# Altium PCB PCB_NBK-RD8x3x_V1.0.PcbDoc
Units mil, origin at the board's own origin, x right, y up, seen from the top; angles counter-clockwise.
Board outline 2760.94 x 3491.25 mil, 2 copper layers (Top Layer, Bottom Layer), stack 21 mil thick; 40 components, 63 nets, 291 pads, 93 vias.
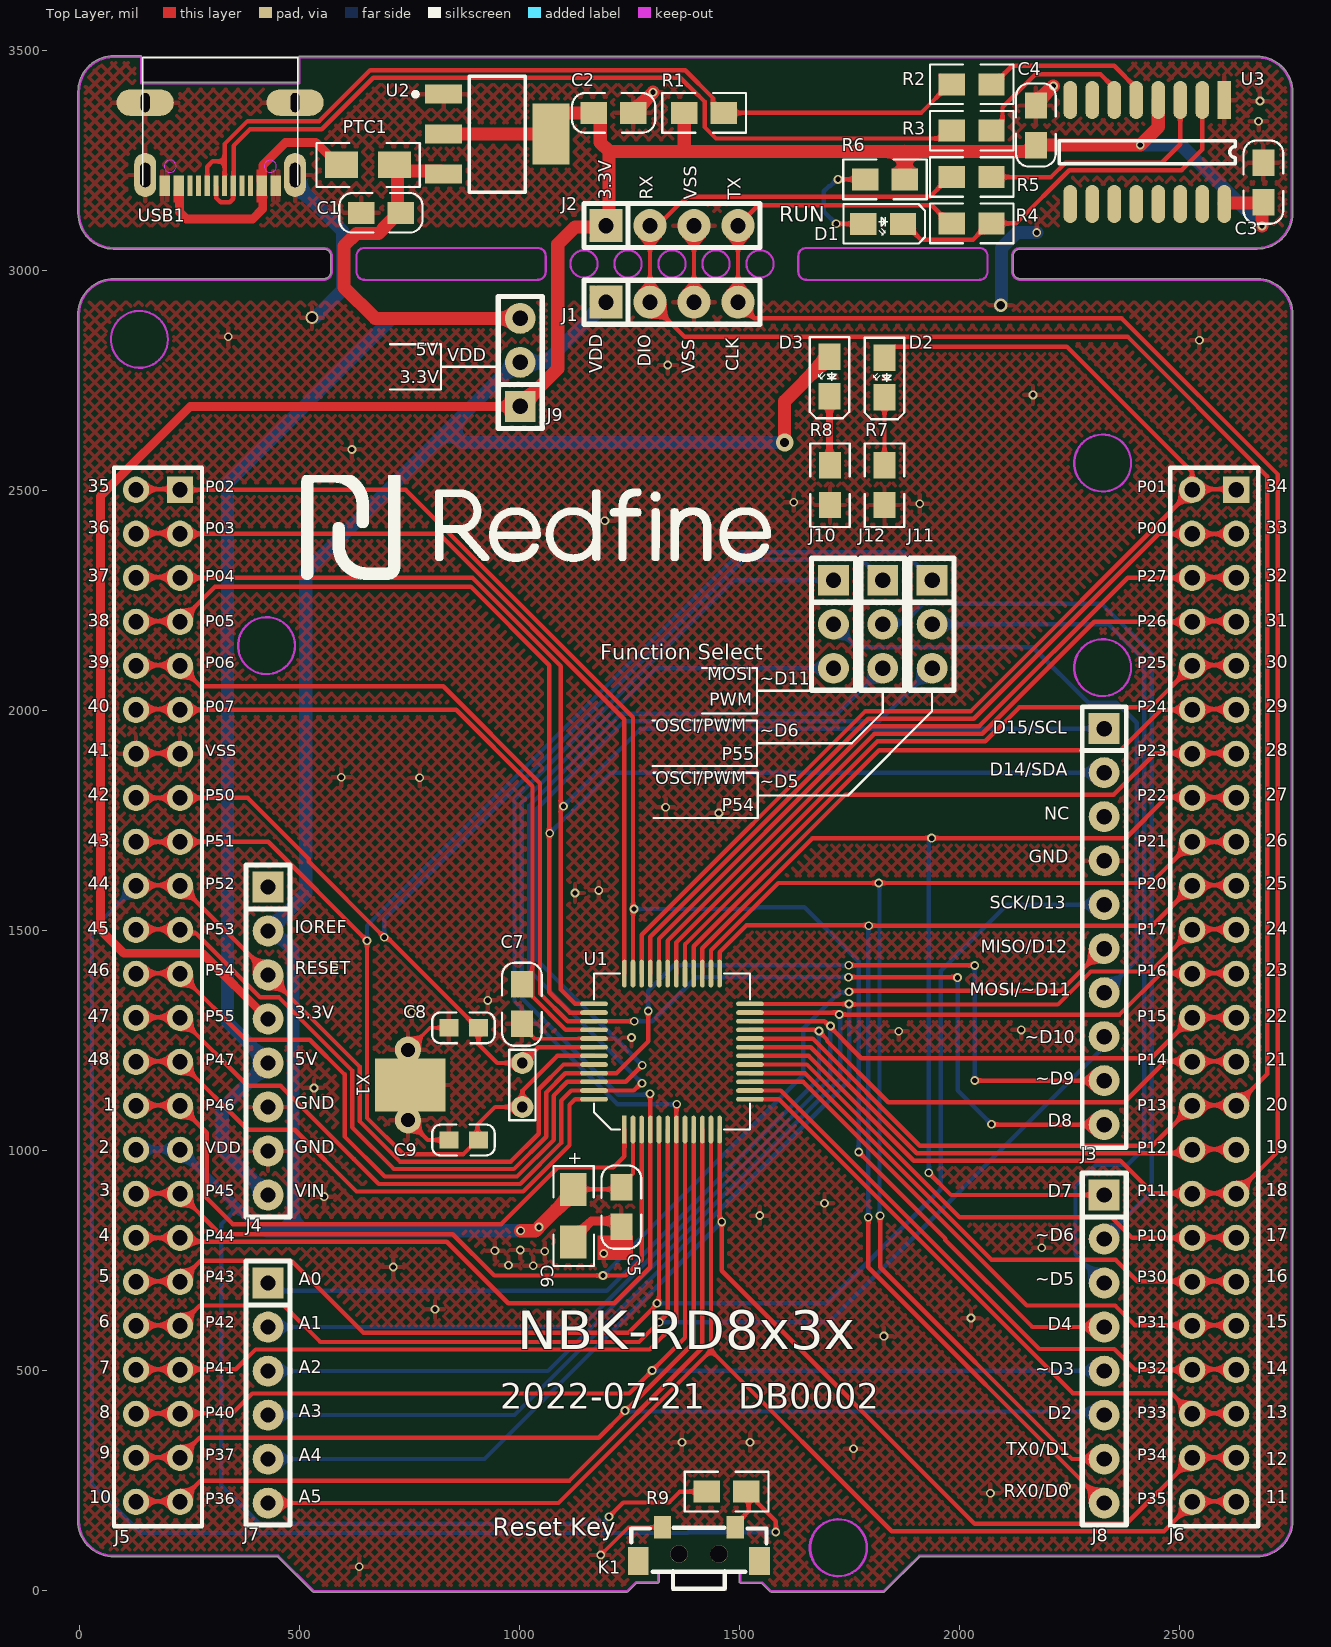
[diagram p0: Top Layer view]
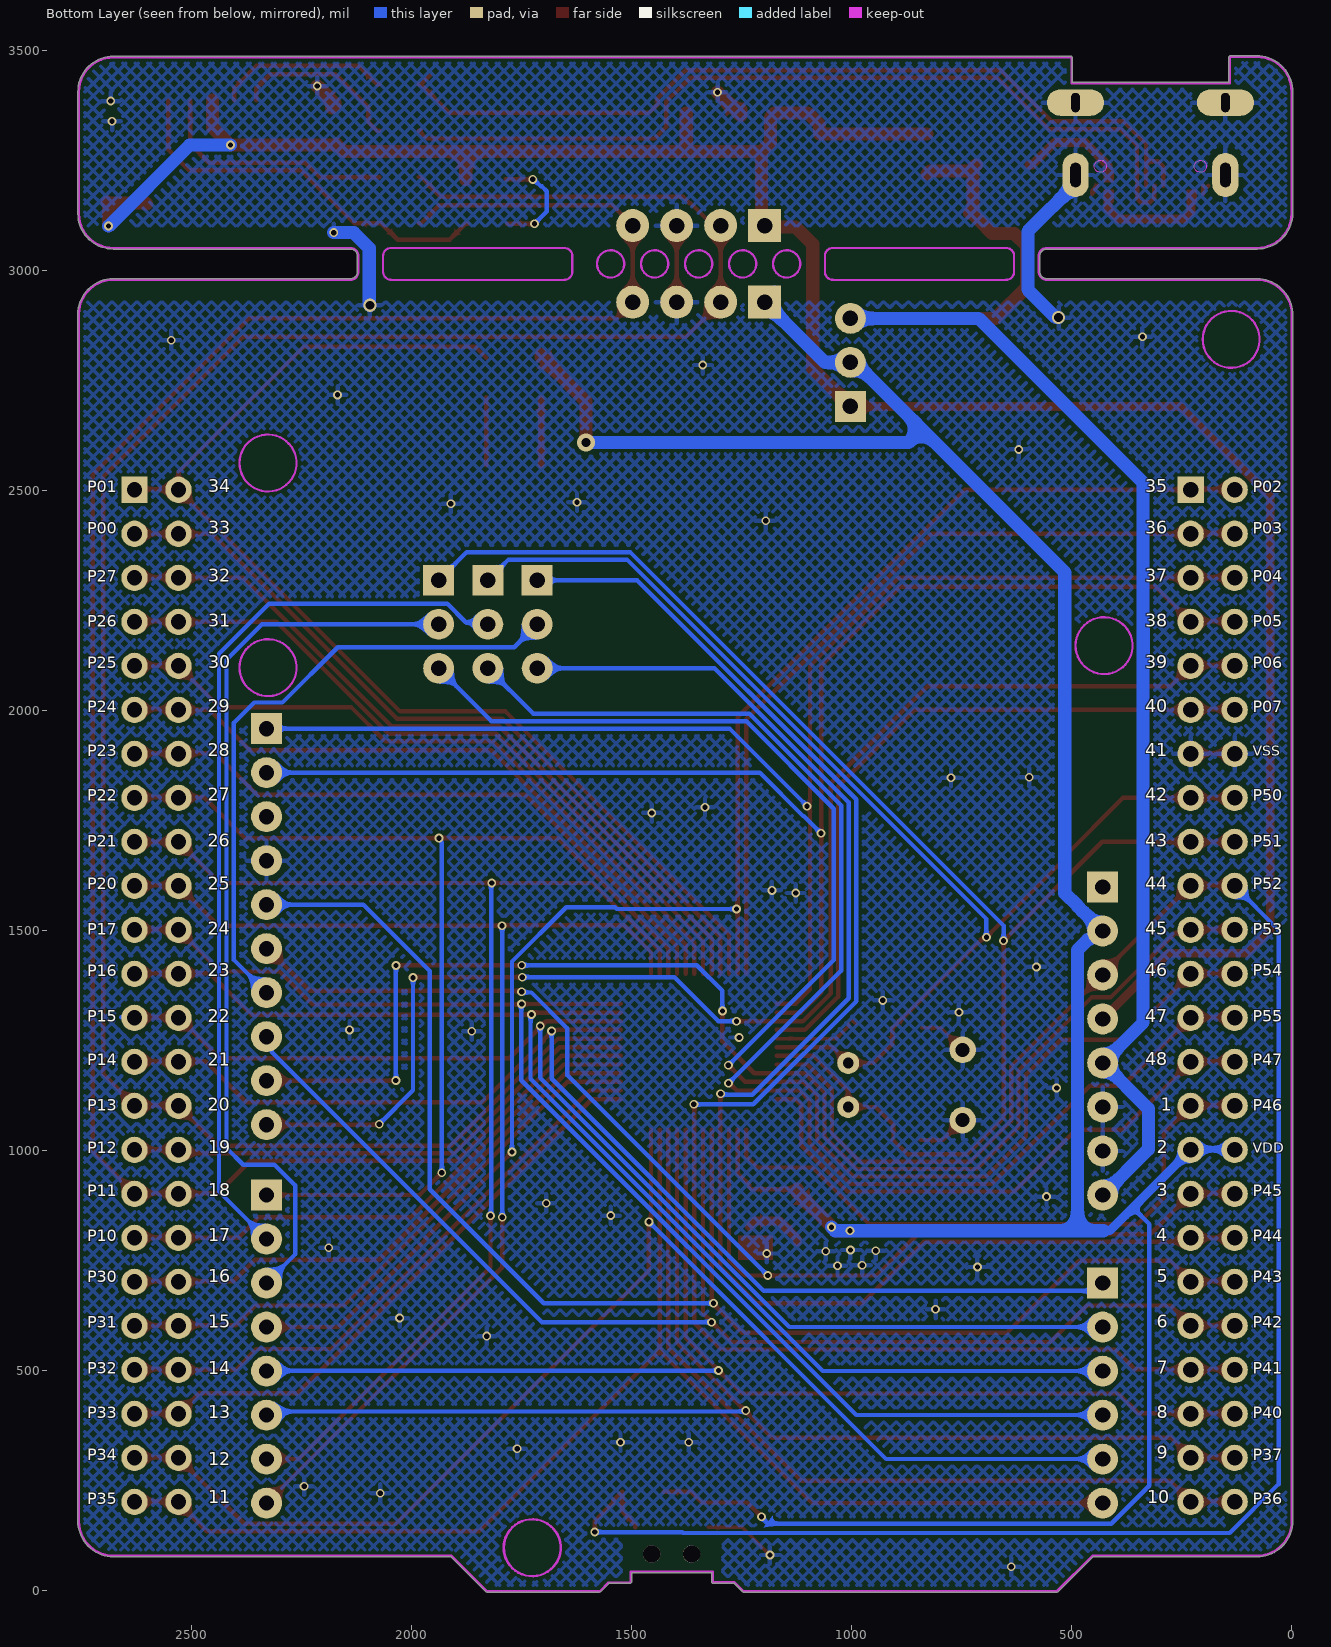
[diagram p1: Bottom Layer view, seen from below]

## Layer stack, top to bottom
Top Solder: solder mask 0.4, Solder Resist, Dk 3.5
Top Layer: signal copper 1.4
Dielectric 1: prepreg 2.8, PP-006, Dk 4.1
Dielectric1: dielectric 12.6, FR-4, Dk 4.8
Dielectric 2: prepreg 2.8, PP-006, Dk 4.1
Bottom Layer: signal copper 1.4
Bottom Solder: solder mask 0.4, Solder Resist, Dk 3.5

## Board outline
78.06,76.8 451.03,76.8 530.62,-2.79 532.39,-3.52 1245.4,-3.52 1247.18,-2.78 1266.44,16.48 1315,16.48 1317.51,19 1317.51,40.49 1499.49,40.49 1499.49,18.73 1502.36,16.21 1550.92,16.21 1570.18,-3.05 1573.1,-3.52 1828.45,-3.52 1830.23,-2.78 1909.81,76.8 2676.48,76.8 ccw(c2676.48,158.06) 2757.74,158.05 2757.74,2900.58 ccw(c2677.03,2900.58) 2677.58,2981.28 2676.95,2981.37 2138.15,2981.37 cw(c2138.15,2997) 2122.51,2997 2122.51,3033 cw(c2138.15,3033) 2138.15,3048.63 2676.95,3048.63 ccw(c2676.95,3129.34) 2757.66,3129.34 2757.66,3405.93 ccw(c2676.95,3405.93) 2676.95,3486.64 500,3486.64 497.49,3484.12 497.49,3427.52 142.51,3427.52 142.51,3485 139.78,3487.74 78.35,3487.74 ccw(c78.35,3406.48) -2.91,3406.48 -2.91,3129.89 ccw(c78.35,3129.89) 78.22,3048.63 555.95,3048.63 cw(c555.95,3033) 571.59,3033 571.59,2997 cw(c555.95,2997) 555.95,2981.37 555.06,2981.2 78.06,2981.2 ccw(c78.05,2899.94) -3.03,2905.23 -3.2,2904.31 -3.2,159 -3.2,158.05 ccw(c78.06,158.05)

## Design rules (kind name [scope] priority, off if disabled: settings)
Clearance Clearance_2 [(InComponent('U1') AND IsPad)] p1: gap=6 ignorepadtopadclearanceinfootprint=FALSE except(0: Arc-Hole Track-Hole SMDPad-Hole THPad-Hole Via-Hole Fill-Hole Poly-Hole Region-Hole Text-Hole)
Clearance Clearance_1 [All] p2: gap=7 ignorepadtopadclearanceinfootprint=FALSE except(0: Arc-Hole Track-Hole SMDPad-Hole THPad-Hole Via-Hole Fill-Hole Poly-Hole Region-Hole Text-Hole)
ComponentClearance [All] p1 off: gap=10 collisioncheckmode=3 verticalgap=10 showdistances=FALSE
Height [All] p1 off: minheight=0 maxheight=1000 prefheight=500
HoleSize [All] p1: absolutevalues=TRUE maxlimit=150 minlimit=1 maxpercent=80.000 minpercent=20.000
MinimumSolderMaskSliver [All] p1: minsoldermaskwidth=0
PolygonConnect [All] p1: connectstyle=Relief reliefconductorwidth=10 reliefentries=4 polygonreliefangle="90 Angle" airgapwidth=10
RoutingVias [All] p1: holewidth=28 width=50 viastyle="Through Hole" minholewidth=10 minwidth=20 maxholewidth=130 maxwidth=180
SilkToSilkClearance [All] p1 off: silktosilkclearance=0
SilkToSolderMaskClearance [IsPad] p1 off: minsilkscreentomaskgap=0 clearancetoexposedcopper=TRUE
SolderMaskExpansion [All] p1: expansion=4 istentingtop=FALSE
Width [All] p1: maxlimit=30 minlimit=5 preferedwidth=7
24 further rules are at their usual default settings.

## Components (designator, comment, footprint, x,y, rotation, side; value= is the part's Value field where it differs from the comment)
C1 "104" C0805 731,3131 r180 top
C2 "104" C0805 1169,3358 r0 top
C3 "104" C0805 2691,3155.2 r90 top
C4 "104" C0805 2174,3285 r90 top
C5 "104" C0805 1232,917 r270 top
C6 "10uF" A-3216 1123,912 r270 top
C7 "103" C0805 1006,1378 r270 top
C8 "10pF" C0603 907,1279 r180 top
C9 "10pF" C0603 907,1024 r180 top
D1 "LED-GREED" LED0805 1827,3106 r0 top
D2 "LED-GREED" LED0805 1830,2757 r270 top
D3 "LED-GREED" LED0805 1705,2759 r270 top
J1 "CON1*4" CON1*4(P=2.54) 1347,2928 r0 top
J2 "CON1*4" CON1*4(P=2.54) 1347,3102 r0 top
J3 "CON1*10" CON1*10(P=2.54) 2329,1509 r270 top
J4 "CON1*8" CON1*8(P=2.54) 429,1249 r270 top
J5 "CON2*24" CON2*24(P=2.54) 194,1351.5 r270 top
J6 "CON2*24" CON2*24(P=2.54) 2594,1351.5 r270 top
J7 "CON1*6" CON1*6(P=2.54) 429,449 r270 top
J8 "CON1*8" CON1*8(P=2.54) 2329,549 r270 top
J9 "CON1*3" CON1*3(P=2.54) 1002,2791 r90 top
J10 "CON1*3" CON1*3(P=2.54) 1714,2196 r270 top
J11 "CON1*3" CON1*3(P=2.54) 1938,2196 r270 top
J12 "CON1*3" CON1*3(P=2.54) 1826,2196 r270 top
K1 "单路开关" SW-SMD_UK-B0246-SP25Y 1408.28,105.64 r180 top
PTC1 "0.5A 6V 自恢复保险丝" R1206 596,3240 r0 top
R1 "1.5K" R0805 1375,3358 r0 top
R2 "22R" R0805 1983,3423 r0 top
R3 "22R" R0805 1983,3317.67 r0 top
R4 "100R" R0805 2073,3107 r180 top
R5 "100R" R0805 2073,3212.33 r180 top
R6 "2.2K" R0805 1876,3207 r180 top
R7 "5.1K" R0805 1830,2557 r270 top
R8 "5.1K" R0805 1706,2557 r270 top
R9 "1.5K" R0805 1516,225 r180 top
U1 "RD8T37P48" LQFP-48(7X7) 1347,1225 r90 top (schematic designator U?)
U2 "AMS1117-3.3V" SOT-223 950,3310 r270 top
U3 "CH340C" SOP16 2602,3387.22 r270 top
USB1 "TYPE-C" TYPE-C1 320.22,3287.01 r0 top
X1 "32.768K" 32768 1007,1199 r270 top

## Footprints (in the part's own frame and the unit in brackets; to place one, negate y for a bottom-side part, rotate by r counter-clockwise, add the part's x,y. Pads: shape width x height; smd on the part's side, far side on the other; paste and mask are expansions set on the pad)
32768 [mil] "32.768KHZ"
  round 60 hole 32: 0(-30,-260) 0(130,-260)
  rect 120x160 smd: 0(50,-255)
  round 50 hole 24: 1(0,0) 2(100,0)
  silkscreen extent -30,-30 130,30
A-3216 [mil]
  rect 75x60 smd: 1(0,0) 2(120,0)
  silkscreen extent -53,-45 174,47
C0603 [mm]
  rect 1.1x1 smd: 1(0,0) 2(1.7,0)
  silkscreen extent -0.94,-0.89 2.67,0.89
C0805 [mil]
  rect 60x50 smd: 1(0,0) 2(90,0)
  silkscreen extent -49,-45 140,45
CON1*3(P=2.54) [mil]
  rect 70x70 hole 35: 1(-100,0)
  round 70 hole 35: 2(0,0) 3(100,0)
  silkscreen extent -150,-50 150,50
CON1*4(P=2.54) [mil]
  rect 75x75 hole 35: 1(-150,0)
  round 75 hole 35: 2(-50,0) 3(50,0) 4(150,0)
  silkscreen extent -200,-50 200,50
CON1*6(P=2.54) [mil]
  rect 70x70 hole 35: 1(-250,0)
  round 70 hole 35: 2(-150,0) 3(-50,0) 4(50,0) 5(150,0) 6(250,0)
  silkscreen extent -300,-50 300,50
CON1*8(P=2.54) [mil]
  rect 70x70 hole 35: 1(-350,0)
  round 70 hole 35: 2(-250,0) 3(-150,0) 4(-50,0) 5(50,0) 6(150,0) 7(250,0) 8(350,0)
  silkscreen extent -400,-50 400,50
CON1*10(P=2.54) [mil]
  rect 70x70 hole 35: 1(-450,0)
  round 70 hole 35: 2(-350,0) 3(-250,0) 4(-150,0) 5(-50,0) 6(50,0) 7(150,0) 8(250,0) 9(350,0) 10(450,0)
  silkscreen extent -500,-50 502,50
CON2*24(P=2.54) [mil]
  rect 60x60 hole 35: 1(-1150,35)
  round 60 hole 35: 2(-1150,-65) 3(-1050,35) 4(-1050,-65) 5(-950,35) 6(-950,-65) 7(-850,35) 8(-850,-65) 9(-750,35) 10(-750,-65) 11(-650,35) 12(-650,-65) 13(-550,35) 14(-550,-65) 15(-450,35) 16(-450,-65) 17(-350,35) 18(-350,-65) 19(-250,35) 20(-250,-65) 21(-150,35) 22(-150,-65) 23(-50,35) 24(-50,-65) 25(50,35) 26(50,-65) 27(150,35) 28(150,-65) 29(250,35) 30(250,-65) 31(350,35) 32(350,-65) 33(450,35) 34(450,-65) 35(550,35) 36(550,-65) 37(650,35) 38(650,-65) 39(750,35) 40(750,-65) 41(850,35) 42(850,-65) 43(950,35) 44(950,-65) 45(1050,35) 46(1050,-65) 47(1150,35) 48(1150,-65)
  silkscreen extent -1200,-115 1205,85
LED0805 [mil]
  rect 60x50 smd: 1(-45,0) 2(45,0)
  silkscreen extent -90,-45 95,45
LQFP-48(7X7) [mm]
  rect 1.6x0.27 smd: 1(-4.5,2.75)
  oval 1.6x0.27 smd: 2(-4.5,2.25) 3(-4.5,1.75) 4(-4.5,1.25) 5(-4.5,0.75) 6(-4.5,0.25) 7(-4.5,-0.25) 8(-4.5,-0.75) 9(-4.5,-1.25) 10(-4.5,-1.75) 11(-4.5,-2.25) 12(-4.5,-2.75) 25(4.5,-2.75) 26(4.5,-2.25) 27(4.5,-1.75) 28(4.5,-1.25) 29(4.5,-0.75) 30(4.5,-0.25) 31(4.5,0.25) 32(4.5,0.75) 33(4.5,1.25) 34(4.5,1.75) 35(4.5,2.25) 36(4.5,2.75)
  oval 0.27x1.6 smd: 13(-2.75,-4.5) 14(-2.25,-4.5) 15(-1.75,-4.5) 16(-1.25,-4.5) 17(-0.75,-4.5) 18(-0.25,-4.5) 19(0.25,-4.5) 20(0.75,-4.5) 21(1.25,-4.5) 22(1.75,-4.5) 23(2.25,-4.5) 24(2.75,-4.5) 37(2.75,4.5) 38(2.25,4.5) 39(1.75,4.5) 40(1.25,4.5) 41(0.75,4.5) 42(0.25,4.5) 43(-0.25,4.5) 44(-0.75,4.5) 45(-1.25,4.5) 46(-1.75,4.5) 47(-2.25,4.5) 48(-2.75,4.5)
  silkscreen extent -4.5,-4.5 4.5,4.5
R0805 [mil]
  rect 60x50 smd: 1(0,0) 2(90,0)
  silkscreen extent -50,-45 140,45
R1206 [mil]
  rect 75x60 smd: 1(0,0) 2(120,0)
  silkscreen extent -57,-50 178,50
SOP16 [mm]
  rect 2.2x0.8 smd: 1(0,0)
  oval 2.2x0.8 smd: 2(0,-1.27) 3(0,-2.54) 4(0,-3.81) 5(0,-5.08) 6(0,-6.35) 7(0,-7.62) 8(0,-8.89) 9(6,-8.89) 10(6,-7.62) 11(6,-6.35) 12(6,-5.08) 13(6,-3.81) 14(6,-2.54) 15(6,-1.27) 16(6,0)
  silkscreen extent 2.33,-9.53 3.67,0.64
SOT-223 [mm]
  rect 1.1x2.15 smd: 1(-2.3,-3.1) 2(0,-3.1) 3(2.3,-3.1)
  rect 3.5x2.15 smd: 2(0,3.1)
  silkscreen extent -3.35,-4.85 3.35,1.63
SW-SMD_UK-B0246-SP25Y [mm]
  rect 1x1.3 smd: 1(2.1,-0.975) 2(-2.1,-0.975)
  rect 1.2x1.6 smd: 3(-3.5,0.975) 4(3.5,0.975)
  round 1 hole 1 unplated: ""(-1.15,0.575) ""(1.15,0.575)
  silkscreen extent -3.9,-0.95 3.9,2.57
TYPE-C1 [mm]
  oval 3.302x1.524 / inner oval 1.27x2.54 / far side oval 3.302x1.524 hole 0.5 slot 1.1 at 90 deg: 1(-4.325,2.4) 3(4.325,2.4)
  oval 1.27x2.54 / inner oval 1.27x2.54 / far side oval 1.524x2.54 hole 0.6 slot 1.4 at 90 deg: 2(-4.325,-1.78) 4(4.325,-1.78)
  rect 0.3x1.2 smd: A1(3.355,-2.4) A4(2.555,-2.4) A5(1.255,-2.4) A6(0.255,-2.4) A7(-0.245,-2.4) A8(-1.245,-2.4) A9(-2.545,-2.4) A12(-3.345,-2.4) B1(-3.045,-2.4) B4(-2.245,-2.4) B5(-1.745,-2.4) B6(-0.745,-2.4) B7(0.755,-2.4) B8(1.755,-2.4) B9(2.255,-2.4) B12(3.055,-2.4)
  Keep-Out Layer circle w0.05: c-2.885,-1.28 r0.35
  Keep-Out Layer circle w0.05: c2.895,-1.28 r0.35
  silkscreen extent -4.47,-2.35 4.48,5

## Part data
C1 C2 C3 C4 C5 C7 C8 C9: library part CAP1, "贴片电容"
C6: library part T-A/4.7uF/16V
D1 D2: library part LED-CP, "蓝色"
D3: library part LED-CP, "红色"
K1: library part KEY-6
PTC1: library part PTC-MZ11-06A200-400RM, "6V 500mA PTC自恢复保险丝"
R1 R2 R3 R4 R5 R6 R7 R8 R9: library part R0805
U1: "电压:2.0V-5.5V;ROM:128KB;RAM:内部256B+外部8KB+ PWM&LCD 80B;32/16/8/4MHz"
U2: library part LDO-SPX1117M3, "LDO；1A；SOT-223-3"
USB1: library part TYPE-C1, "Type-c母座16pin 快充闪充usb3.0沉板母座连接器"
X1: library part CRYSTAL

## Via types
v1: diameter 20, hole 12, Top Layer to Bottom Layer, 90 vias
v2: diameter 30, hole 20, Top Layer to Bottom Layer, 2 vias
v3: diameter 40, hole 20, Top Layer to Bottom Layer, tented both sides, 1 vias

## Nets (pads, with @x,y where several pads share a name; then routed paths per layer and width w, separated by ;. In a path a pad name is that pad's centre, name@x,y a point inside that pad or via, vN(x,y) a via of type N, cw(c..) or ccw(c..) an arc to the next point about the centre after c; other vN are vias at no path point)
3.3V: C2.1 C3.1 C4.1 J2.1 J4.4 J9.1 R1.1 R6.1 U2.2 U3.4 U3.16 | length 5682
  Top Layer w20: J4.4 279.5,1448.5 101.5,1448.5 48,1502 48,2486.97 252.03,2691 J9.1
  Top Layer w30: U2.2@827.95,3310 1072.05,3310 1072.05,3330.68 1099.37,3358 C2.1 1174,3358 1184,3348 1184,3290.67 1204,3270.67 ; J9.1 1087.5,2776.5 1087.5,3059.5 1127,3099 1194,3099 J2.1 1204,3109 1204,3270.67 ; R1.1 1375,3270.67 ; R6.1 1876,3270.67 ; C4.1@2170,3285 v1(2411,3285) 2452,3326 U3.4 ; C4.1@2170,3287 2153.67,3270.67 1876,3270.67 ; U3.16 2602,3152.41 2602.69,3153.1 C3.1@2688.9,3153.1 ; v1(2688,3101) 2688,3152.2 C3.1@2688.9,3153.1 ; C3.1 C3.1@2688.9,3153.1 ; 1204,3270.67 1375,3270.67 ; 1375,3270.67 1876,3270.67
  Bottom Layer w30: J2.1@1174.5,3079.5 J2.1 ; v1(2411,3285) 2504,3285 v1(2688,3101)
5V: C1.1 J4.5 J4.8 J9.3 PTC1.2 U2.3 | length 3483.2
  Top Layer w30: U2.3 821.3,3226.1 729.9,3226.1 PTC1.2 723.5,3232.5 723.5,3138.5 C1.1 726,3131 693,3098 693,3096.89 680.06,3083.94 629.94,3083.94 601.6,3055.6 601.6,2962 672.6,2891 J9.3
  Bottom Layer w30: J4.8 325,1003 325,1095 J4.5 337,1291 337,2109.95 336.48,2110.47 336.48,2184.38 337,2184.9 337,2517.33 710.67,2891 J9.3
A0: J6.27 J6.28 J7.1 U1.21 | length 2788
  Top Layer w10: U1.21 1669.78,1274.21 1670.19,1273.81 1679.17,1273.81 v1(1681.08,1271.9) 1681.08,1270.27 1699.17,1252.18 1699.17,1249.19 1838.36,1110 2374.87,1110 2467.87,1203 J6.27@2629,1203
  Bottom Layer w10: J7.1 447,681 1198.88,681 1681.08,1163.21 v1(1681.08,1271.9) ; J6.27@2629,1197 J6.27 J6.27@2629,1203
A1: J6.25 J6.26 J7.2 U1.22 | length 2838.5
  Top Layer w10: U1.22 1693.4,1293.9 1777.29,1210 2436,1210 2529,1303 J6.25@2629,1303
  Bottom Layer w10: J7.2 1140.92,599 1707,1165.08 v1(1707,1283) ; J6.25@2629,1303 2659,1303
A2: J6.23 J6.24 J7.3 U1.23 | length 2877.9
  Top Layer w10: J7.3 J7.3@438.77,489.23 ; U1.23 1719.71,1313.58 1722.38,1310.91 v1@1724.33,1310.91 ; v1(1727,1309) 2364,1309 2458,1403 J6.23@2629,1403
  Bottom Layer w10: J7.3 1064.96,499 1729,1163.04 1729,1292.11 1728.91,1292.2 1728.91,1307.09 v1(1727,1309)
A3: J6.21 J6.22 J7.4 U1.24 | length 2983.5
  Top Layer w10: J7.4@426,399 J7.4 ; U1.24 1524.29,1333.15 1749.06,1333.15 v1(1749.21,1333) ; v1@1753.85,1333.15 1755,1332 2224,1332 2299,1407 2434.5,1407 J6.22 ; J6.22@2529,1503 J6.21@2629,1503
  Bottom Layer w10: J7.4 989,399 1750,1160 1750,1332.21 v1(1749.21,1333)
A4: J6.45 J6.46 J7.5 U1.12 | length 3046.4
  Top Layer w10: U1.12 1455.27,845.44 1460,840.71 1460,726.58 2034.58,152 2379.5,152 J6.46 ; J6.46@2529,303 J6.45@2629,303
  Bottom Layer w10: J7.5 921,299 v1(1460,838)
A5: J6.47 J6.48 J7.6 U1.11 | length 3046.4
  Top Layer w10: J7.6 1089,199 1435.58,545.58 ; U1.11 1435.58,545.58 ; J6.47@2629,203 2529,203 J6.48 2529,199 2465,135 1846.17,135 1435.58,545.58
CLK: J1.4 J2.4 J6.33 J6.34 R4.2 U1.18 | length 4992.1
  Top Layer w10: U1.18 1657.97,1215.16 1896.12,977 2366,977 2440,903 2529,903 2629,903 2724,998 2724,2536.28 2369.28,2891 1534.25,2891 1497.25,2928 J1.4 J2.4 1543,3148 1937,3148 1978,3107 R4.2
CMOD: C7.1 J5.11 J5.12 U1.40 | length 1622.3
  Top Layer w10: J5.12@129,2003 J5.11@229,2003 ; J5.11 856.46,2001.5 1030,1827.96 1030,1349.92 1105.7,1274.21 U1.40 U1.40@1169.96,1274.09
D2: J5.45 J5.46 J8.6 U1.9 | length 2965.8
  Top Layer w10: J5.46@129,303 229,303 273.5,347.5 1180.39,347.5 1240,407.11 v1(1240,409) 1241.89,409 1396.21,563.33 U1.9
  Bottom Layer w10: J5.45@229,291 J5.45@229,303 ; v1(1240,409) 1241.91,407.09 2320.91,407.09 J8.6
D4: J5.1 J5.2 J8.4 U1.35 | length 3646.4
  Top Layer w10: J5.2@129,2503 J5.1@229,2503 ; J5.1 741.62,2501.5 1258.42,1984.71 U1.35 ; v1(1771.21,996.94) 1968.18,799.97 1968.18,796.82 2166,599 J8.4
  Bottom Layer w10: v1(1260.73,1549) 1533,1549 1537,1553 1647.88,1553 1771.21,1429.67 v1(1771.21,996.94)
D7: J6.15 J6.16 J8.1 U1.27 | length 2607.3
  Top Layer w10: U1.27 1415.9,1459.73 1666.17,1710 2378,1710 2471,1803 J6.15@2629,1803 ; v1(1930.6,949.6) 1981.2,899 J8.1
  Bottom Layer w10: v1(1930.6,949.6) 1930.6,1700.89 1937,1707.29 v1(1937,1710) ; J6.16@2529,1791 J6.16 J6.16@2529,1803
D8: J3.10 J5.9 J5.10 U1.39 | length 3161.7
  Top Layer w10: J5.10@129,2103 J5.9@229,2103 ; J5.9 275.5,2055 827,2055 1047,1835 1047,1356.96 1110.06,1293.9 U1.39 1169.89,1293.95 1260.95,1293.95 v1(1261,1294) ; v1(1748,1394) 1995,1394 v1(1996,1393) ; v1(2073,1060) 2074,1059 J3.10
  Bottom Layer w10: v1(1261,1294) 1302,1294 1402,1394 v1(1748,1394) ; v1(1996,1393) 1996,1137 v1(2073,1060) ; J3.10@2317,1047 J3.10
D13: J6.31 J6.32 U1.19 | length 1207.7
  Top Layer w10: U1.19 1662.32,1234.84 1903.17,994 2521.5,994 J6.32 ; J6.32@2529,1003 J6.31@2629,1003
D+: R1.2 R2.1 USB1.A6 USB1.B6 | length 2008.3
  Top Layer w10: USB1.B6 290.89,3235.89 303,3248 330.26,3248 ; USB1.A6 330.26,3248 ; R2.1@1958,3443 R2.1@1978,3423 ; R2.1 R2.1@1978,3423 ; 330.26,3248 330.26,3287.3 382.45,3339.5 545.45,3339.5 660.96,3455 1377,3455 1440,3392 1440,3378 1460,3358 1913,3358 R2.1@1978,3423
D-: R3.1 USB1.A7 USB1.B7 | length 1994.6
  Top Layer w10: USB1.A7 311.48,3191.61 311.48,3164.8 321.28,3155 342,3155 349.94,3162.94 USB1.B7 350.85,3193.43 350.85,3283.85 388,3321 551,3321 668,3438 1366,3438 1405.26,3398.74 1406.24,3398.74 1421,3383.97 1421,3326 1447,3300 1965.33,3300 R3.1 R3.1@1978,3317.67
DIO: J1.2 J2.2 J6.29 J6.30 R5.2 U1.20 | length 5174.3
  Top Layer w10: U1.20 1666.68,1254.53 1910.21,1011 2438.5,1011 J6.30 ; R5.2 1978,3212.33 1932.78,3167.11 1381.89,3167.11 1367.91,3153.13 1365.67,3153.13 1314.54,3102 J2.2 J1.2 1376,2849 2383,2849 2700,2532 2700,1174 2629,1103 J6.30@2529,1103
GND: C1.2 C2.2 C3.2 C4.2 C5.2 C6.2 C7.2 C8.2 C9.2 J1.3 J2.3 J3.4 J4.6 J4.7 J5.13 J5.14 K1.1 R7.2 R8.2 U1.41 U2.1 U3.1 USB1.1 USB1.2 USB1.3 USB1.4 USB1.A1 USB1.A12 USB1.B1 USB1.B12 X1.0 | length 1846.1
  Top Layer w8: X1.0@747,1229 797,1279 C8.2 ; C7.2@990,1288 C7.2@997.53,1295.53 ; C7.2 1006,1283 1034.47,1254.53 U1.41 ; v1(1185,81) 1248.02,144.02 K1.1
  Top Layer w10: J5.14@129,1903 J5.13@229,1903 ; USB1.A12 USB1.A12@189.43,3191.61 ; USB1.B1@200.34,3174.8 USB1.B1 ; USB1.B12 452.56,3180.46 452.56,3174.55 USB1.A1@453.18,3173.9 ; X1.0@747,1069 792,1024 C9.2 C9.2@842,1024 ; J1.3 J2.3
  Top Layer w20: C6.2 1123,799.5 1163.5,840 1219,840 C5.2
  Top Layer w30: C2.2 C2.2@1258,3359 ; v1(1304,3405) C2.2@1258,3359 ; C4.2 2174,3380 C4.2@2181,3387 ; C4.2@2181,3370 C4.2@2181,3387 ; v1@2214.25,3419 v1(2213.63,3419) 2213,3419 C4.2@2181,3387 ; C2.2@1258,3359 1251,3352 1251,3366 C2.2@1258,3359
  Bottom Layer w30: USB1.4 490.5,3196.93 598.6,3088.82 598.6,2956.6 535,2893 v2(529,2893) ; v2(2094,2921) 2095.5,2922.5 2095.5,3050.67 2130.83,3086 v1(2176,3086)
  other v1: 636.49,54.29 2070.49,221.29 2243.49,237.29 1759.49,322.29 1369.49,337.29 1524.49,337.29 1828.49,578.29 2026.49,619.29 808.49,639.29 713.49,735.29 1031.49,738.29 975.49,739.29 1192,766 1058,771 944.49,772.29 1002,774 2187.49,779.29 1546.49,852.29 1693.49,880.29 556.49,895.29 533.49,1142.29 1255,1257 1862.49,1271.29 2140.49,1274.29 755.49,1314.29 928.49,1341.29 579.49,1417.29 1126.49,1585.29 1180.49,1591.29 1453.49,1767.29 1332.49,1780.29 773.49,1847.29 595.49,1848.29 1194.49,2431.29 1910,2470 1623.49,2473.29 619.49,2593.29 2167.49,2717.29 1337.49,2785.29 2545.49,2841.29 338.49,2849.29 2680,3339 2683,3385
IOREF: C5.1 C6.1 D3.1 J1.1 J4.2 J5.31 J5.32 J9.2 R9.2 U1.2 | length 6752.3
  Top Layer w10: C6.1 C5.1@1227,912 ; v1(1204,168) 1236.33,200.33 1340.37,200.33 1365.04,225 R9.2 ; C5.1@1232.18,917.18 1232.18,922.18 1252,942 1252.56,942 1258.42,947.86 U1.2
  Top Layer w30: v1(1003,818) 1037,818 v1(1045,826) 1045,826.5 1123,904.5 C6.1 ; v3(1603,2609) 1603,2703 D3.1@1689,2789 ; D3.1 D3.1@1705,2809
  Bottom Layer w10: 360.25,870.25 323,833 323,238.53 409.53,152 1189.72,152 1204,166.28 v1(1204,168)
  Bottom Layer w15: J5.32@129,1003 229,1003 J5.31
  Bottom Layer w20: J5.31 360.25,870.25 412.85,817.65 427,817.65
  Bottom Layer w30: 427,817.65 486,817.65 ; v1@1003,817.65 486,817.65 ; v1(1003,818) 1037,818 v1(1045,826) ; J1.1@1174.5,2950.5 J1.1 1060,2791 J9.2 992,2791 840,2639 ; v3(1603,2609) 870,2609 840,2639 ; 486,817.65 486,1456 462.57,1479.43 459.39,1479.43 439.82,1499 J4.2 472,1542 473.11,1542 486,1554.89 486,1556 514.91,1584.91 514.91,2313.91 840,2639
MISO: J3.6 J5.33 J5.34 U1.3 | length 3047.6
  Top Layer w10: J5.34@129,903 229,903 229.75,902.25 J5.33 320.5,810 849,810 943,716 v1(1190,716) 1241.96,716 1278.1,752.14 U1.3 ; v1(1749.21,1361.09) 1751.12,1363 2230.96,1363 2326.96,1459 J3.6
  Bottom Layer w10: v1(1190,716) 1645.51,1171.51 1645.51,1277.63 1727.06,1359.17 1747.3,1359.17 v1(1749.21,1361.09)
MOSI: J5.35 J5.36 J10.3 U1.4 | length 3341.1
  Top Layer w10: J5.36 J5.35 237.5,793 835,793 975,653 1216,653 1297.79,734.79 U1.4 1297.67,1047.96 1297.67,1128.33 v1(1297,1129)
  Bottom Layer w10: J5.35 J5.35@243.5,787 ; v1(1297,1129) 1295.09,1127.09 1224.91,1127.09 1006,1346 1006,1791.08 1310.92,2096 J10.3
NetD1_1: D1.1 R6.2 | length 252.8
  Top Layer w10: v1(1720,3106) D1.1 ; v1(1724,3207) R6.2
  Bottom Layer w10: v1(1720,3106) 1692,3134 1692,3180 1702.94,3190.94 1705.24,3190.94 1721.29,3207 v1(1724,3207)
NetD2_2: D2.2 R7.1 | length 155
  Top Layer w10: R7.1 D2.2
NetD3_2: D3.2 R8.1 | length 152.4
  Top Layer w15: D3.2@1705,2709 1705,2558 R8.1
P00: J6.3 J6.4 U1.33 | length 1793.9
  Top Layer w10: U1.33 1297.79,1485.87 1792.92,1981 2032.54,1981 2453.04,2401.5 2527.5,2401.5 2529,2403 2530.5,2401.5 J6.3@2627.5,2401.5
P01: D2.1 J6.1 J6.2 U1.34 | length 2724.2
  Top Layer w10: U1.34 1278.1,1490.23 1785.88,1998 2025.5,1998 J6.2 ; D2.1 1855,2827 2244,2827 2529,2542 2529,2503 J6.1@2629,2503
P03: J5.3 J5.4 U1.36 | length 1862.4
  Top Layer w10: J5.4@129,2403 J5.3@229,2403 ; J5.3 817.58,2401.5 1238.73,1980.35 U1.36
P10: J6.35 J6.36 U1.17 | length 1268
  Top Layer w10: U1.17 1653.61,1195.47 2001.08,848 2346.47,848 2392.97,801.5 J6.36 ; J6.36@2529,803 J6.35@2629,803
P23: J6.13 J6.14 U1.28 | length 1476.5
  Top Layer w10: U1.28 1396.21,1464.09 1741.12,1809 2351,1809 2445,1903 2529,1903 J6.13@2629,1903
P24: J6.11 J6.12 U1.29 | length 1539.6
  Top Layer w10: U1.29 1376.53,1468.44 1818.08,1910 2366.97,1910 2458.47,2001.5 J6.12 ; J6.12@2529,2003 J6.11@2629,2003
P25: J6.9 J6.10 U1.30 | length 1603.2
  Top Layer w10: U1.30 1356.84,1472.8 1814.04,1930 2059,1930 2136,2007 2434.5,2007 J6.10 ; J6.10@2529,2103 J6.9@2629,2103
P26: J6.7 J6.8 U1.31 | length 1667.5
  Top Layer w10: U1.31 1337.16,1477.16 1807,1947 2051.96,1947 2306.46,2201.5 2527.5,2201.5 2529,2203 J6.7@2629,2203
P27: J6.5 J6.6 U1.32 | length 1730.5
  Top Layer w10: U1.32 1317.47,1481.51 1799.96,1964 2044.92,1964 2382.42,2301.5 J6.6 ; J6.6@2529,2303 J6.5@2629,2303
P30: J6.37 J6.38 U1.16 | length 1300.7
  Top Layer w10: U1.16 1649.25,1175.79 2073.04,752 2355,752 2404,703 2529,703 J6.37@2629,703
P31: J6.39 J6.40 U1.15 | length 1333.9
  Top Layer w10: U1.15 1644.9,1156.1 2153,648 2354,648 2399,603 2529,603 J6.39@2629,603
P32: J6.41 J6.42 U1.14 | length 1367.8
  Top Layer w10: U1.14 1594.31,1136.42 2181.73,549 2352.13,549 2399.63,501.5 J6.42 ; J6.42@2529,503 J6.41@2629,503
P33: J6.43 J6.44 U1.13 | length 1401.1
  Top Layer w10: U1.13 1589.95,1116.73 2258.15,448.53 2481.97,448.53 J6.44 ; J6.44@2529,403 J6.43@2629,403
P36: J5.47 J5.48 U1.10 | length 1927.4
  Top Layer w10: J5.48@129,203 229,203 276,250 1114,250 1415.9,551.9 U1.10
P46: J5.29 J5.30 U1.1 | length 1432.7
  Top Layer w10: J5.30@129,1103 J5.29@229,1103 ; J5.29 290,1040.5 290,892 349,833 959,833 1087.5,961.5 1213.5,961.5 1238.73,986.73 U1.1
P47: J5.27 J5.28 U1.48 | length 1303.6
  Top Layer w10: J5.28@129,1203 J5.27@229,1203 ; J5.27 383,1047.5 489.5,1047.5 630,907 1008.96,907 1114,1012.04 1114,1104 1126.73,1116.73 U1.48
P54: J5.23 J5.24 J11.3 U1.46 | length 3301.1
  Top Layer w10: J5.24@129,1403 229,1403 J5.23@229.75,1402.25 ; J5.23 378.5,1252 524,1252 603,1173 603,1032 694,941 994.88,941 1078,1024.12 1078,1124.96 1109.14,1156.1 U1.46 1241.74,1156.1 v1(1279.39,1193.76)
  Bottom Layer w10: v1(1279.39,1193.76) 1040,1433.15 1040,1777 1239,1976 1818,1976 J11.3
P55: J5.25 J5.26 J12.3 U1.47 | length 3126.6
  Top Layer w10: J5.26@129,1303 J5.25@229,1303 ; J5.25 383,1147.5 457.5,1147.5 623.94,981.06 623.94,979.94 ; 625,979.88 680.88,924 1001.92,924 1095,1017.08 1095,1113.48 1117.94,1136.42 U1.47 1260.23,1136.42 1276.81,1153 v1(1279,1153)
  Bottom Layer w10: v1(1279,1153) 1023,1409 1023,1784.04 1231.96,1993 1723,1993 J12.3
PWM/OSCI: C8.1 J5.15 J5.16 J12.1 U1.42 X1.1 | length 2862.5
  Top Layer w10: J5.16 J5.15 382.53,1801.5 521.31,1662.72 521.31,1656.69 694.97,1483.03 701,1483.03 905.03,1279 C8.1 907,1242 950,1199 X1.1 1042.84,1234.84 U1.42
  Bottom Layer w10: v1(693.06,1484.94) 693.06,1526.22 1509.83,2343 1779,2343 J12.1
PWM/OSCO: C9.1 J5.17 J5.18 J11.1 U1.43 X1.2 | length 3404.5
  Top Layer w7: C9.1@905.03,1041.52 905.03,1025.97 C9.1
  Top Layer w10: J5.18 J5.17 429.5,1701.5 v1(654,1477) 654,1074.04 736.04,992 873.03,992 905.03,1024 C9.1 ; C9.1@905.03,1041.52 905.03,1059.03 945,1099 X1.2 1007,1136 1086.16,1215.16 U1.43
  Bottom Layer w10: v1(654,1477) 654,1511.21 1502.79,2360 1874,2360 J11.1
RESET: J4.3 J5.19 J5.20 K1.2 R9.1 U1.44 | length 4739.1
  Top Layer w10: J5.20@129,1603 229,1603 429,1403 J4.3 637,1191 637,1067 729,975 980.79,975 1044,1038.21 1044,1139.04 1100.43,1195.47 U1.44 ; K1.2 1490.96,149.93 1521,179.97 1521,225 1541,205 1541,200 1583,158 v1(1583,133)
  Bottom Layer w10: J5.20 29,1501.5 29,242.1 140.1,131 1382.53,131 1384.53,133 v1(1583,133)
RX: R5.1 U3.3 | length 560.3
  Top Layer w10: R5.1 2073.19,3212.14 2208.14,3212.14 2241,3245 2460,3245 2502,3287 U3.3
RX0: J6.19 J6.20 J8.8 U1.25 | length 2822.1
  Top Layer w10: U1.25 1455.27,1451.02 1516.25,1512 1793,1512 v1(1794,1511) 2438.5,1511 J6.20 ; v1(1793.21,848.65) 1793.21,734.79 J8.8 ; J6.20@2529,1603 2627.5,1603 J6.19
  Bottom Layer w10: v1(1793.21,848.65) 1793.21,1510.21 v1(1794,1511) ; J6.19 J6.19@2630.5,1601.5
SCK: J3.5 J5.37 J5.38 U1.5 | length 3382.8
  Top Layer w10: J5.38@129,703 229,703 276,750 482,750 646,586 1248,586 1317.47,655.47 U1.5
  Bottom Layer w10: J5.37@229,703 J5.37@233,703 ; v1(1313,653) 1698.96,653 1958,912.04 1958,1408 2109,1559 J3.5
SCL: J3.1 J5.5 J5.6 U1.37 | length 3183.2
  Top Layer w10: J5.6@129,2303 229,2303 J5.5@230.5,2301.5 ; J5.5 J5.5@230.5,2301.5 ; v1(1100.62,1782.38) 1100.34,1782.66 v1@1094,1782.66 ; U1.37 1169.71,1333.39 1126.61,1333.39 1094,1366 v1@1094,1782.66 ; J5.5@230.5,2301.5 893.54,2301.5 1094,2101.04 v1@1094,1782.66
  Bottom Layer w10: v1(1100.62,1782.38) 1100.62,1782.94 1276.68,1959 J3.1
SDA: J3.2 J5.7 J5.8 U1.38 | length 3227.3
  Top Layer w10: J5.8@129,2203 J5.7@229,2203 ; J5.7 308.5,2281 890,2281 1068,2103 1068,1722 v1(1069,1721) ; v1@1068,1721 1068,1360 1114.42,1313.58 U1.38
  Bottom Layer w10: v1(1069,1721) 1108.38,1760.38 1109.73,1760.38 1208.35,1859 J3.2
TX: D1.2 R4.1 U3.2 | length 892
  Top Layer w10: D1.2 1877,3106 1913,3070 2031,3070 2068,3107 R4.1 2129,3107 2250,3228 2505,3228 2552,3275 U3.2
TX0: J6.17 J6.18 J8.7 U1.26 | length 2912.4
  Top Layer w10: U1.26 1435.58,1455.37 1588.21,1608 v1(1817,1608) 2435.5,1608 J6.18 J6.17 ; v1(1820,852) 1820,735 2256,299 J8.7
  Bottom Layer w10: v1(1817,1608) 1818.5,1606.5 1818.5,853.5 v1(1820,852)
USB_D+: R2.2 U3.5 | length 394.8
  Top Layer w10: R2.2 2078,3423 2120,3465 2351.78,3465 2402,3414.78 U3.5
USB_D-: R3.2 U3.6 | length 392.2
  Top Layer w10: R3.2 2078,3317.67 2098,3337.67 2098,3370.97 2173.03,3446 2320.78,3446 2352,3414.78 U3.6
VIN: PTC1.1 USB1.A4 USB1.A9 USB1.B4 USB1.B9 | length 511.6
  Top Layer w20: 225,3165 228,3165 228,3133 244,3117 394,3117 417,3140 417,3166.41 417.59,3167 ; 417,3216.5 417,3239 469,3291 537.5,3291 588.5,3240 PTC1.1
~D3: J5.43 J5.44 J8.5 U1.8 | length 2840.4
  Top Layer w10: J5.44@129,403 348,403 393,448 1249.77,448 v1(1301.89,500.11) ; v1@1302,500 1302,500.23 1376.53,574.75 U1.8 ; J8.5@2308,499 J8.5
  Bottom Layer w10: v1(1301.89,500.11) 1302.44,499.56 2328.44,499.56 J8.5
~D5: J8.3 J11.2 | length 2078.8
  Top Layer w10: J8.3 J8.3@2343,699
  Bottom Layer w10: J11.2 2339.15,2196 2420,2115.15 2420,1006 2382,968 2311.03,968 2264,920.97 2264,764 J8.3
~D6: J8.2 J12.2 | length 2083.4
  Top Layer w10: J8.2@2298,799 J8.2
  Bottom Layer w10: J12.2 1830.47,2200.47 1876,2200.47 1918.53,2243 2323,2243 2437,2129 2437,907 J8.2
~D9: J3.9 J5.21 J5.22 U1.45 | length 3084.4
  Top Layer w10: J5.22@129,1503 229,1503 J5.21@229,1501.61 ; J5.21 236.51,1493.99 265.13,1493.99 411.11,1348 454,1348 620,1182 620,1053.04 715.04,958 987.83,958 1061,1031.17 1061,1132 1104.67,1175.67 1169.71,1175.67 U1.45 1169.94,1175.89 1220.89,1175.89 1293,1248 v1(1293,1317) ; v1(1748.78,1420.99) 2034.74,1420.99 v1(2034.96,1420.77) ; v1@2032.66,1159 J3.9
  Bottom Layer w10: v1(1293,1317) 1293,1363 1350.99,1420.99 v1(1748.78,1420.99) ; v1(2034.96,1420.77) v1(2035,1159) v1(2035,1159)
~D10: J3.8 J5.39 J5.40 U1.6 | length 2999.1
  Top Layer w10: J5.40@129,603 229,603 274,648 465,648 548,565 1272,565 1337.16,630.16 U1.6
  Bottom Layer w10: v1(1318,610) 1703,610 2317.52,1224.52 2317.52,1247.52 J3.8
~D11: J5.41 J5.42 J10.1 U1.7 | length 3624.4
  Top Layer w10: J5.42@129,503 355.7,503 400.7,548 1296,548 1356.84,608.84 U1.7 1356.84,1104.04 v1(1357.83,1105.03)
  Bottom Layer w10: v1(1357.83,1105.03) 1222.93,1105.03 989,1338.96 989,1798.12 1486.88,2296 J10.1
~D11/MOSI: J3.7 J10.2 | length 1425.4
  Bottom Layer w10: J10.2 1766,2144 2167.09,2144 2292.88,2018.21 2356.76,2018.21 2403,1971.97 2403,1433 J3.7
pads on no net: J3.3 J4.1 K1. K1.3 K1.4 U3.7 U3.8 U3.9 U3.10 U3.11 U3.12 U3.13 U3.14 U3.15 USB1.A5 USB1.A8 USB1.B5 USB1.B8

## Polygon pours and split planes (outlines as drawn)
GND on Top Layer "NONET_L-01_P-001" (hatched 45Degree grid 20 track 8, remove dead copper, pour order 1): 2954,3102 2954,3555 -160,3555 -160,3102
GND on Top Layer "NONET_L-01_P-001" (hatched 45Degree grid 20 track 8, remove dead copper, pour order 0): 2954,-158 2954,2928 -160,2928 -160,-158
GND on Bottom Layer "NONET_L-01_P-001" (hatched 45Degree grid 20 track 8, remove dead copper, pour order 4): -160,-157 -160,2928 2954,2928 2954,-157
GND on Bottom Layer "NONET_L-01_P-001" (hatched 45Degree grid 20 track 8, remove dead copper, pour order 2): -160,3102 -160,3557 2954,3557 2954,3102

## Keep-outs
Keep-Out Layer:
  circle w5: c1724.69,97.43 r64.72
  circle w5: c1725.69,97.43 r64.72
  circle w5: c425.69,2147.43 r64.72
  circle w5: c2325.69,2097.43 r64.72
  circle w5: c136.69,2843.43 r64.72
  circle w5: c2325.69,2562.43 r64.72
  circle w5: c1147,3015 r31
  circle w5: c1247,3015 r31
  circle w5: c1347,3015 r31
  circle w5: c1447,3015 r31
  circle w5: c1547,3015 r31
  lines w5: -0.68,158.05 ccw(c78.06,158.05) 78.06,79.31 452.07,79.31 532.39,-1 1245.4,-1 1265.4,19 1315,19 1315,43 1348,43 1502,43 1502,18.73 ; -0.69,159 -0.69,2904.31 ; -0.69,2899.94 cw(c78.06,2899.94) 78.06,2978.69 555.79,2978.69 ; 78.22,3051.15 555.95,3051.15 cw(c555.95,3033) 574.1,3033 574.1,2997 cw(c555.95,2997) 555.95,2978.85 ; 78.35,3051.15 cw(c78.35,3129.89) -0.39,3129.89 -0.39,3406.48 cw(c78.35,3406.48) 78.35,3485.22 139.78,3485.22 140,3485 140,3425 500,3425 500,3484.12 2676.95,3484.12 cw(c2676.95,3405.93) 2755.14,3405.93 2755.14,3129.34 cw(c2676.95,3129.34) 2676.95,3051.15 2138.15,3051.15 ccw(c2138.15,3033) 2120,3033 2120,2997 ccw(c2138.15,2997) 2138.15,2978.85 2676.95,2978.85 ; 648.15,2978.69 1041.85,2978.69 ; 648.15,2978.85 cw(c648.15,2997) 630,2997 630,3033 cw(c648.15,3033) 648.15,3051.15 1041.85,3051.15 cw(c1041.85,3033) 1060,3033 1060,2997 cw(c1041.85,2997) 1041.85,2978.85 ; 1502.36,18.73 1551.96,18.73 1571.96,-1.27 ; 1571.96,-1 1828.45,-1 ; 1652.15,2978.69 2045,2978.69 ; 1652.15,2978.85 cw(c1652.15,2997) 1634,2997 1634,3033 cw(c1652.15,3033) 1652.15,3051.15 2045.85,3051.15 cw(c2045.85,3033) 2064,3033 2064,2997 cw(c2045.85,2997) 2045.85,2978.85 ; 1830.02,0.57 1873.45,44 ; 1893.45,64 1828.45,-1 ; 2677.03,2978.77 cw(c2677.03,2900.58) 2755.22,2900.58 2755.22,158.05 cw(c2676.48,158.06) 2676.48,79.31 1908.76,79.31 1828.45,-1

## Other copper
Top Layer:
  rectangle net VIN: 403,3155 427,3184
  region net GND: 1258,807 1178,807 1178,751 1258,751
  rectangle net VIN: 214,3155 238,3184
  rectangle net VIN: 403,3200 427,3229
  pour cut-out: 1084,863 1168,863 1168,750 1084,750
  pour cut-out: 1294.5,146 1517.5,146 1517.5,32 1516.5,33 1295.5,33
Bottom Layer:
  pour cut-out: 1295.5,145 1518.5,145 1518.5,31 1517.5,32 1296.5,32

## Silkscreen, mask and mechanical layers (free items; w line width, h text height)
Top Overlay:
  drawing of 30 lines, arcs and shapes, not listed
  text "3.3V" at 1218.78,3160.95 h50 r90
  text "RX" at 1312.99,3160.95 h50 r90
  text "VSS" at 1412.99,3161 h50 r90
  text "TX" at 1512.99,3160.95 h50 r90
  text "RUN" at 1591,3097.67 h60
  text "5V" at 765,2796.29 h50
  text "VDD" at 836.05,2784.01 h50
  text "DIO" at 1309,2781 h50 r90
  text "CLK" at 1509,2771 h50 r90
  text "VDD" at 1199,2766 h50 r90
  text "VSS" at 1409,2766 h50 r90
  text "3.3V" at 728,2733.22 h50
  text "P02" at 286,2486.54 h46
  text "P01" at 2404,2486.54 h46
  text "35" at 18.93,2485.28 h50
  text "34" at 2696.06,2485.28 h50
  text "P03" at 286,2392.54 h46
  text "P00" at 2404,2392.54 h46
  text "36" at 18.93,2391.28 h50
  text "33" at 2696.06,2391.28 h50
  text "P04" at 286,2283.26 h46
  text "P27" at 2404,2283.01 h46
  text "37" at 18.93,2282 h50
  text "32" at 2696.06,2282 h50
  text "P05" at 286,2181.47 h46
  text "P26" at 2404,2181.47 h46
  text "38" at 18.93,2180.21 h50
  text "31" at 2696.06,2180.21 h50
  text "Function Select" at 1184,2103 h60
  text "P06" at 286,2086.99 h46
  text "P25" at 2404,2086.99 h46
  text "39" at 18.93,2085.72 h50
  text "30" at 2696.06,2085.72 h50
  text "MOSI" at 1427.01,2058.01 h50
  text "~D11" at 1546,2047.95 h50
  text "PWM" at 1431.54,2001.01 h50
  text "P07" at 286,1986.99 h46
  text "P24" at 2404,1986.73 h46
  text "40" at 18.93,1985.72 h50
  text "29" at 2696.01,1985.72 h50
  text "OSCI/PWM" at 1308.6,1941.01 h50
  text "D15/SCL" at 2075.86,1937 h50
  text "~D6" at 1546,1930.22 h50
  text "VSS" at 286.04,1886.8 h46
  text "P23" at 2404,1886.99 h46
  text "28" at 2696.01,1885.72 h50
  text "41" at 18.93,1885.45 h50
  text "P55" at 1459.63,1877.29 h50
  text "D14/SDA" at 2069.27,1842 h50
  text "OSCI/PWM" at 1308.6,1822.01 h50
  text "~D5" at 1546,1814.29 h50
  text "P50" at 286,1786.26 h46
  text "P22" at 2404,1786.01 h46
  text "42" at 18.93,1784.72 h50
  text "27" at 2696.01,1784.72 h50
  text "P54" at 1460,1760.29 h50
  text "NC" at 2192.93,1742 h50
  text "P51" at 286,1681.26 h46
  text "P21" at 2404,1681.01 h46
  text "43" at 18.93,1680 h50
  text "26" at 2696.01,1680 h50
  text "GND" at 2157.74,1644 h50
  text "P52" at 286,1584.26 h46
  text "P20" at 2404,1584.26 h46
  text "44" at 18.93,1582.79 h50
  text "25" at 2696.01,1583 h50
  text "SCK/D13" at 2069.36,1539 h50
  text "IOREF" at 490,1484 h50
  text "P53" at 286,1481.54 h46
  text "P17" at 2404,1481.29 h46
  text "45" at 18.56,1480.35 h50
  text "24" at 2696.01,1480 h50
  text "MISO/D12" at 2048.92,1439 h50
  text "RESET" at 490,1390 h50
  text "P54" at 286,1387.6 h46
  text "P16" at 2404,1387.54 h46
  text "46" at 18.79,1386.28 h50
  text "23" at 2696.01,1386.28 h50
  text "MOSI/~D11" at 2023.2,1342 h50
  text "3.3V" at 490,1289 h50
  text "P55" at 286,1283.33 h46
  text "P15" at 2404,1283.26 h46
  text "47" at 18.79,1281.79 h50
  text "22" at 2696.01,1281.72 h50
  text "~D10" at 2148.18,1234 h50
  text "P47" at 286,1184.35 h46
  text "5V" at 490,1184 h50
  text "P14" at 2404,1184.29 h46
  text "48" at 18.75,1183.28 h50
  text "21" at 2696.01,1183 h50
  text "~D9" at 2172.87,1139 h50
  text "GND" at 490,1084 h50
  text "P46" at 286,1081.26 h46
  text "P13" at 2404,1081.26 h46
  text "1" at 54.18,1079.72 h50
  text "20" at 2696.01,1080 h50
  text "D8" at 2200.59,1044 h50
  text "VDD" at 286.04,985.07 h46
  text "P12" at 2404,985.01 h46
  text "2" at 44.71,983.72 h50
  text "GND" at 490,984 h50
  text "19" at 2696.06,984 h50
  text "P45" at 286,887.6 h46
  text "P11" at 2404,887.29 h46
  text "3" at 45.04,886.28 h50
  text "18" at 2696.06,886.28 h50
  text "VIN" at 490.06,884 h50
  text "D7" at 2200.69,884 h50
  text "P44" at 286,785.07 h46
  text "P10" at 2404,785.26 h46
  text "4" at 43.79,783.79 h50
  text "~D6" at 2172.97,784 h50
  text "17" at 2696.06,783.72 h50
  text "P43" at 286,691.26 h46
  text "P30" at 2404,691.26 h46
  text "5" at 44.76,690.28 h50
  text "16" at 2696.06,690 h50
  text "A0" at 499,684 h50
  text "~D5" at 2172.72,684 h50
  text "P42" at 286,588.01 h46
  text "P31" at 2404,588.26 h46
  text "6" at 44.8,587 h50
  text "15" at 2696.05,587 h50
  text "A1" at 499,584 h50
  text "D4" at 2200.78,582 h50
  text "NBK-RD8x3x" at 995,519 h150
  text "A2" at 499,484 h50
  text "P32" at 2404,483.54 h46
  text "P41" at 286,483.29 h46
  text "7" at 45.27,482.28 h50
  text "14" at 2696.05,482 h50
  text "~D3" at 2172.97,479 h50
  text "2022-07-21   DB0002" at 956.41,394 h100
  text "A3" at 499,384 h50
  text "P40" at 286,382.54 h46
  text "P33" at 2404,382.54 h46
  text "8" at 44.9,381.28 h50
  text "13" at 2696.05,381.28 h50
  text "D2" at 2200.98,379 h50
  text "TX0/D1" at 2106.26,297 h50
  text "9" at 44.94,289 h50
  text "P37" at 286,286.99 h46
  text "P34" at 2404,286.99 h46
  text "A4" at 499,284 h50
  text "12" at 2696.05,274.72 h50
  text "RX0/D0" at 2101.28,202 h50
  text "A5" at 499,189 h50
  text "10" at 23.23,188.28 h50
  text "11" at 2696.05,188 h50
  text "P36" at 286,186.99 h46
  text "P35" at 2404,186.99 h46
  text "Reset Key" at 940,111.15 h70
Bottom Overlay:
  text "P02" at 88,2486.54 h46
  text "P01" at 2736,2486.54 h46
  text "35" at 332.07,2485.28 h50
  text "34" at 2461.94,2485.28 h50
  text "P03" at 88,2392.54 h46
  text "P00" at 2736,2392.54 h46
  text "36" at 332.07,2391.28 h50
  text "33" at 2461.94,2391.28 h50
  text "P04" at 88,2283.26 h46
  text "P27" at 2736,2283.01 h46
  text "37" at 332.07,2282 h50
  text "32" at 2461.94,2282 h50
  text "P05" at 88,2181.47 h46
  text "P26" at 2736,2181.47 h46
  text "38" at 332.07,2180.21 h50
  text "31" at 2461.94,2180.21 h50
  text "P06" at 88,2086.99 h46
  text "P25" at 2736,2086.99 h46
  text "39" at 332.07,2085.72 h50
  text "30" at 2461.94,2085.72 h50
  text "P07" at 88,1986.99 h46
  text "P24" at 2736,1986.73 h46
  text "40" at 332.07,1985.72 h50
  text "29" at 2461.99,1985.72 h50
  text "VSS" at 87.96,1888.7 h40
  text "P23" at 2736,1886.99 h46
  text "28" at 2461.99,1885.72 h50
  text "41" at 332.07,1885.45 h50
  text "P50" at 88,1786.26 h46
  text "P22" at 2736,1786.01 h46
  text "42" at 332.07,1784.72 h50
  text "27" at 2461.99,1784.72 h50
  text "P51" at 88,1681.26 h46
  text "P21" at 2736,1681.01 h46
  text "43" at 332.07,1680 h50
  text "26" at 2461.99,1680 h50
  text "P52" at 88,1584.26 h46
  text "P20" at 2736,1584.26 h46
  text "44" at 332.07,1582.79 h50
  text "25" at 2461.99,1583 h50
  text "P53" at 88,1481.54 h46
  text "P17" at 2736,1481.29 h46
  text "45" at 332.44,1480.35 h50
  text "24" at 2461.99,1480 h50
  text "P54" at 88,1387.6 h46
  text "P16" at 2736,1387.54 h46
  text "46" at 332.21,1386.28 h50
  text "23" at 2461.99,1386.28 h50
  text "P55" at 88,1283.33 h46
  text "P15" at 2736,1283.26 h46
  text "47" at 332.21,1281.79 h50
  text "22" at 2461.99,1281.72 h50
  text "P47" at 88,1184.35 h46
  text "P14" at 2736,1184.29 h46
  text "48" at 332.25,1183.28 h50
  text "21" at 2461.99,1183 h50
  text "P46" at 88,1081.26 h46
  text "P13" at 2736,1081.26 h46
  text "1" at 296.82,1079.72 h50
  text "20" at 2461.99,1080 h50
  text "VDD" at 87.96,986.98 h40
  text "P12" at 2736,985.01 h46
  text "2" at 306.29,983.72 h50
  text "19" at 2461.94,984 h50
  text "P45" at 88,887.6 h46
  text "P11" at 2736,887.29 h46
  text "3" at 305.96,886.28 h50
  text "18" at 2461.94,886.28 h50
  text "P44" at 88,785.07 h46
  text "P10" at 2736,785.26 h46
  text "4" at 307.21,783.79 h50
  text "17" at 2461.94,783.72 h50
  text "P43" at 88,691.26 h46
  text "P30" at 2736,691.26 h46
  text "5" at 306.24,690.28 h50
  text "16" at 2461.94,690 h50
  text "P42" at 88,588.01 h46
  text "P31" at 2736,588.26 h46
  text "6" at 306.2,587 h50
  text "15" at 2461.95,587 h50
  text "P32" at 2736,483.54 h46
  text "P41" at 88,483.29 h46
  text "7" at 305.73,482.28 h50
  text "14" at 2461.95,482 h50
  text "P40" at 88,382.54 h46
  text "P33" at 2736,382.54 h46
  text "8" at 306.1,381.28 h50
  text "13" at 2461.95,381.28 h50
  text "9" at 306.06,289 h50
  text "P37" at 88,286.99 h46
  text "P34" at 2736,286.99 h46
  text "12" at 2461.95,274.72 h50
  text "10" at 327.77,188.28 h50
  text "11" at 2461.95,188 h50
  text "P36" at 88,186.99 h46
  text "P35" at 2736,186.99 h46
Mechanical 1:
  circle w5: c1725,97 r64.72
  circle w5: c2325.69,2097.43 r64.72
  circle w5: c425.69,2147.43 r64.72
  circle w5: c2325.69,2562.43 r64.72
  circle w5: c136.69,2843.43 r64.72
  circle w5: c1347,3015 r31
  circle w5: c1447,3015 r31
  circle w5: c1547,3015 r31
  circle w5: c1247,3015 r31
  circle w5: c1147,3015 r31
  lines w5: -0.68,158.05 ccw(c78.06,158.05) 78.06,79.31 452.07,79.31 ; -0.69,159 -0.69,2904.31 ; -0.69,2899.94 cw(c78.06,2899.94) 78.06,2978.68 555.79,2978.68 ; 78.22,3051.15 555.95,3051.15 cw(c555.95,3033) 574.1,3033 574.1,2997 cw(c555.95,2997) 555.95,2978.85 ; 78.35,3051.15 cw(c78.35,3129.89) -0.39,3129.89 -0.39,3406.48 cw(c78.35,3406.48) 78.35,3485.22 139.78,3485.22 140,3485 140,3425 500,3425 500,3484.12 2676.95,3484.12 cw(c2676.95,3405.93) 2755.14,3405.93 2755.14,3129.34 cw(c2676.95,3129.34) 2676.95,3051.15 2138.15,3051.15 ccw(c2138.15,3033) 2120,3033 2120,2997 ccw(c2138.15,2997) 2138.15,2978.85 2676.95,2978.85 ; 648.15,2978.68 1041.85,2978.68 ; 648.15,2978.85 cw(c648.15,2997) 630,2997 630,3033 cw(c648.15,3033) 648.15,3051.15 1041.85,3051.15 cw(c1041.85,3033) 1060,3033 1060,2997 cw(c1041.85,2997) 1041.85,2978.85 ; 1502,18.73 1502,43 1348,43 1315,43 1315,19 1265.4,19 1245.4,-1 532.39,-1 ; 1502.36,18.73 1551.96,18.73 1571.96,-1.27 ; 1571.96,-1 1828.45,-1 ; 1652.15,2978.69 2045,2978.69 ; 1652.15,2978.85 cw(c1652.15,2997) 1634,2997 1634,3033 cw(c1652.15,3033) 1652.15,3051.15 2045.85,3051.15 cw(c2045.85,3033) 2064,3033 2064,2997 cw(c2045.85,2997) 2045.85,2978.85 ; 1830.02,0.57 1873.45,44 ; 1893.45,64 1828.45,-1 ; 2677.03,2978.77 cw(c2677.03,2900.58) 2755.22,2900.58 2755.22,158.05 ; 452.07,79.31 532.39,-1 ; 452.07,79.31 532.39,-1 ; 1828.45,-1 1908.76,79.31 2676.48,79.31 ; 2676.48,79.31 ccw(c2676.48,158.05) 2755.22,158.05 ; 2676.48,79.31 ccw(c2676.48,158.06) 2755.22,158.05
